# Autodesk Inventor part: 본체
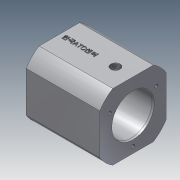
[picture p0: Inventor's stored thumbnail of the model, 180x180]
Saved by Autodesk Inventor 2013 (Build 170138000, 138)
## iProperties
Created: 2020-02
Part Number: 본체
Material: 알루미늄 6061
Document SubType Name: Modeling
Designer: user
Density: 2.71 g/cm^3
Mass: 539.883 g
Surface Area: 342.742 cm^2
Volume: 199.219 cm^3
Author: user
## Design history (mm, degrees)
sketch "스케치1"
  geometry: L1 (-32, -32)-(32, -32); L2 (32, -32)-(32, 32); L3 (32, 32)-(-32, 32); L4 (-32, 32)-(-32, -32); L5 (-32, -32)-(32, 32); L6 (32, -32)-(-32, 32); 1 further point
  constraints: 12 end point, 2 midpoint, 2 parallel, 1 horizontal, 1 perpendicular
  dimensions: "d0" = 64 distance of L3.end L2.end; "d1" = 64 distance of L1.end L2.end
extrude "돌출1" new body sketch "스케치1" distance "d2" = 71; taper "d3" = 0 deg
sketch "스케치2"
  geometry: C1 r 14 at (0, 0); 1 further point
  constraints: 1 centre point, 1 coincident
  dimensions: "d4" = 28 diameter of C1
extrude "돌출2" join sketch "스케치2" distance "d5" = 12; taper "d6" = 0 deg
chamfer "모따기1" distance "d7" = 1; stored, may be unused: second distance "d8" = 2, angle "d9" = 45 deg
sketch "스케치3"
  geometry: C1 r 37.5 at (0, 0); 1 further point
  constraints: 1 centre point, 1 coincident
  dimensions: "d10" = 75 diameter of C1
extrude "돌출3" sketch "스케치3" distance "d11" = 83; taper "d12" = 0 deg
sketch "스케치4"
  geometry: C1 r 20 at (0, 0); A1 r 37.5 centre (0, 0) between (32, 19.551) and (19.551, 32) reference
  constraints: 1 centre point, 1 coincident
  dimensions: "d13" = 40 diameter of C1
extrude "돌출4" cut sketch "스케치4" distance "d14" = 62; taper "d15" = 0 deg
chamfer "모따기2" distance "d16" = 1.8; stored, may be unused: second distance "d17" = 2, angle "d18" = 15 deg
sketch "스케치5"
  geometry: L1 (0, 0)-(0, -26); C1 r 20.482 at (0, 0) reference; A1 r 37.5 centre (0, 0) between (-19.551, 32) and (-32, 19.551) reference; 1 further point
  constraints: 2 end point, 1 coincident, 1 vertical alignment
  dimensions: "d19" = 26 distance of L1.start L1.end
hole "구멍1" sketch "스케치5" at (0, -26) diameter "d20" = 3.242; stored, may be unused: countersink angle "d24" = 90 deg, drill point angle "d26" = 118 deg; dims "d21" = 10, "d22" = 4, "d23" = 2, "d25" = 12
sketch "스케치6"
  geometry: L1 (32, -19.551)-(32, 19.551) reference; L2 (0, 0)-(0, 26); C1 r 14 at (0, 0) reference; 1 further point
  constraints: 2 end point, 1 coincident, 1 parallel
  dimensions: "d30" = 26 distance of L2.start L2.end
hole "구멍2" sketch "스케치6" at (0, 26) diameter "d31" = 3.242; stored, may be unused: countersink angle "d35" = 90 deg, drill point angle "d37" = 118 deg; dims "d32" = 10, "d33" = 4, "d34" = 2, "d36" = 12
sketch "스케치7"
  geometry: C1 r 13 at (0, 0) reference; C2 r 2 at (0, 0)
  constraints: 1 centre point, 1 coincident
  dimensions: "d41" = 4 diameter of C2
extrude "돌출5" cut sketch "스케치7" stored distance "d42" = 62; taper "d43" = 0 deg
sketch "스케치8"
  geometry: C1 r 13 at (0, 0) reference; 1 further point
  constraints: 1 coincident
hole "구멍3" sketch "스케치8" at (0, 0) diameter "d44" = 8.917; stored, may be unused: countersink angle "d48" = 90 deg, drill point angle "d50" = 118 deg; dims "d45" = 14, "d46" = 4, "d47" = 2, "d49" = 17
sketch "스케치9"
  geometry: L1 (39.102, 0)-(0, 0) reference; 3 further points
  constraints: 1 midpoint, 1 vertical alignment
  dimensions: "d51" = 17 distance of point (19.551, 0) point (19.551, -17)
hole "구멍4" sketch "스케치9" at (19.551, -17) diameter "d52" = 8.917; stored, may be unused: countersink angle "d56" = 90 deg, drill point angle "d58" = 118 deg; dims "d53" = 6, "d54" = 4, "d55" = 2, "d57" = 9
sketch "스케치10"
  geometry: C1 r 4.458 at (19.551, -17) reference; C2 r 2 at (19.551, -17); 1 further point
  constraints: 1 centre point, 1 coincident
  dimensions: "d59" = 4 diameter of C2
extrude "돌출6" cut sketch "스케치10" stored distance "d60" = 62; taper "d61" = 0 deg
sketch "스케치11"
  geometry: L1 (39.102, 0)-(0, 0) reference; L2 (0, -71)-(-12.449, -71) reference; 3 further points
  constraints: 1 midpoint, 1 vertical alignment, 1 other
  dimensions: "d62" = 20 vertical distance of L2.end point (19.551, -51)
feature "엠보싱1" sketch "스케치11" dims "d0" = 64, "d1" = 64, "d63" = 0.5, "d64" = 0
node "솔리드1"
pattern_circular "원형 패턴1" dims angle "d28" = 360 deg
pattern_circular "원형 패턴2" dims angle "d39" = 360 deg
